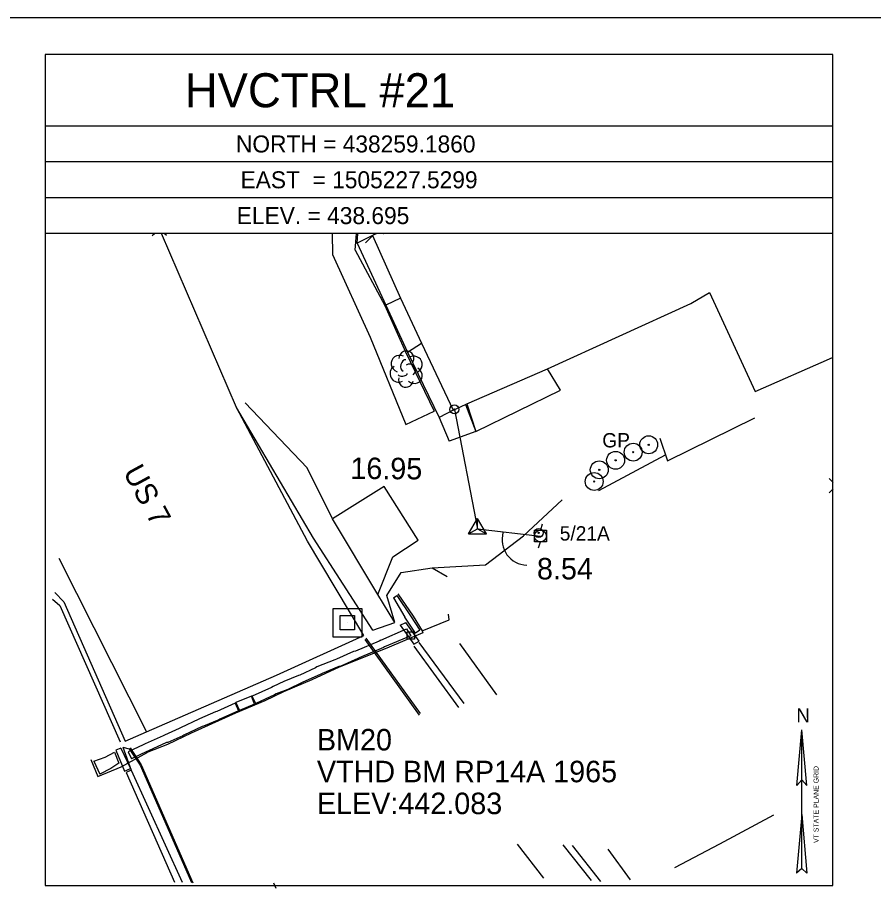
# Model space of a CAD drawing. Extents: x 1504239 to 1504879, y 438007 to 438427.
# Drawn here: x 1504390.4 to 1504509.9, y 438178.8 to 438300.4 of the extents above; entities that cross this region are included whole.
import ezdxf

# ---------------------------------------------------------------- set-up
doc = ezdxf.new("R2010")
doc.units = 0
for name, color, linetype in [('BDC', 7, 'Continuous'), ('BELB', 7, 'Continuous'), ('BF', 7, 'Continuous'), ('BR', 7, 'Continuous'), ('BSE', 7, 'Continuous'), ('BSUBM', 7, 'Continuous'), ('CBP', 7, 'Continuous'), ('CPBM', 7, 'Continuous'), ('CPSM', 7, 'Continuous'), ('Default', 7, 'Continuous'), ('DS', 7, 'Continuous'), ('L_TIC', 7, 'Continuous'), ('LAWE', 7, 'Continuous'), ('LBC', 7, 'Continuous'), ('LBF', 7, 'Continuous'), ('LDEFAULT', 7, 'Continuous'), ('LFNC', 7, 'Continuous'), ('LSH', 7, 'Continuous'), ('LW', 7, 'Continuous'), ('NBL2', 7, 'Continuous'), ('NNA_P', 7, 'Continuous'), ('P_TIC', 7, 'Continuous'), ('PET', 7, 'Continuous'), ('PSP', 7, 'Continuous'), ('R_A', 7, 'Continuous'), ('RDG', 7, 'Continuous'), ('RGP', 7, 'Continuous'), ('RGR', 7, 'Continuous'), ('RSW', 7, 'Continuous'), ('U_C', 7, 'Continuous'), ('UP', 7, 'Continuous'), ('UW', 7, 'Continuous')]:
    doc.layers.add(name, color=color, linetype=linetype)

msp = doc.modelspace()

# ---------------------------------------------------------------- linework, layer by layer
at = {"layer": 'BDC'}
for points in [[(1504439.02, 438213.73), (1504446.6, 438203.21)], [(1504405.08, 438198.52), (1504405.97, 438198.25), (1504407.53, 438196), (1504414.67, 438179.63)], [(1504460.16, 438184.96), (1504463.82, 438180.22)]]:
    msp.add_lwpolyline(points, dxfattribs=at)
at = {"layer": 'BELB'}
for points in [[(1504438.91, 438213.51), (1504446.49, 438202.97)], [(1504406.14, 438198.4), (1504407.65, 438196.02), (1504414.88, 438179.58)], [(1504426.53, 438178.76), (1504426.19, 438179.52)]]:
    msp.add_lwpolyline(points, dxfattribs=at)
at = {"layer": 'BF'}
for points in [[(1504446.42, 438213.09), (1504452.7, 438204.59)], [(1504405.08, 438198.52), (1504406.28, 438195.31), (1504405.56, 438194.98), (1504412.32, 438179.66)], [(1504467.85, 438184.78), (1504471.79, 438179.77)]]:
    msp.add_lwpolyline(points, dxfattribs=at)
at = {"layer": 'BR'}
for points in [[(1504443.84, 438215.51), (1504445.72, 438212.86), (1504446.47, 438213.29), (1504444.63, 438215.9)], [(1504443.84, 438215.51), (1504444.63, 438215.9)], [(1504445.71, 438212.58), (1504451.97, 438204.02)], [(1504404.81, 438198.38), (1504404.1, 438198.1), (1504405.34, 438195.14), (1504406.16, 438195.5)], [(1504404.81, 438198.38), (1504406.16, 438195.5)], [(1504406.28, 438195.31), (1504413.4, 438179.66)], [(1504466.55, 438184.88), (1504470.48, 438179.9)]]:
    msp.add_lwpolyline(points, dxfattribs=at)
at = {"layer": 'BSE'}
for points in [[(1504441.13, 438213.42), (1504444.71, 438215.03), (1504445.32, 438214.06), (1504441.65, 438212.49), (1504441.49, 438212.43), (1504438.1, 438210.97), (1504437.9, 438210.87), (1504435.56, 438209.82), (1504435.26, 438209.74), (1504432.93, 438208.79), (1504432.67, 438208.64), (1504430.22, 438207.56), (1504430.15, 438207.51), (1504428.12, 438206.56), (1504426.51, 438205.93), (1504426.27, 438205.79), (1504423.65, 438204.61), (1504423.5, 438204.52), (1504421.41, 438203.61), (1504421.25, 438203.59), (1504418.64, 438202.41), (1504418.5, 438202.33), (1504416.36, 438201.42), (1504416.18, 438201.37), (1504413.59, 438200.17), (1504413.48, 438200.08), (1504411.36, 438199.17), (1504411.21, 438199.13), (1504408.66, 438197.97), (1504408.43, 438197.88), (1504406.32, 438196.88)], [(1504441.13, 438213.42), (1504440.88, 438213.31), (1504437.59, 438211.91), (1504437.33, 438211.83), (1504434.94, 438210.78), (1504434.71, 438210.7), (1504432.19, 438209.7), (1504431.99, 438209.59), (1504429.81, 438208.57), (1504429.62, 438208.48), (1504427.56, 438207.68), (1504426.1, 438206.96), (1504425.85, 438206.84), (1504423.14, 438205.63), (1504423.04, 438205.63), (1504420.88, 438204.72), (1504420.77, 438204.62), (1504418.21, 438203.48), (1504418.05, 438203.42), (1504415.78, 438202.45), (1504415.72, 438202.41), (1504413.14, 438201.19), (1504412.97, 438201.1), (1504410.89, 438200.17), (1504410.71, 438200.09), (1504408.19, 438198.97), (1504407.93, 438198.84), (1504405.84, 438197.87), (1504406.32, 438196.88)], [(1504423.5, 438204.52), (1504423.04, 438205.63)], [(1504423.65, 438204.61), (1504423.14, 438205.63)], [(1504420.77, 438204.62), (1504421.25, 438203.59)], [(1504420.88, 438204.72), (1504421.41, 438203.61)]]:
    msp.add_lwpolyline(points, dxfattribs=at)
at = {"layer": 'BSUBM'}
for points in [[(1504443.5, 438219.88), (1504445.65, 438216.77), (1504446.91, 438214.75), (1504446.97, 438214.46), (1504441.98, 438212.32), (1504435.32, 438209.66), (1504431.51, 438207.88), (1504427.55, 438206.2), (1504424.91, 438204.98), (1504420.84, 438203.26), (1504414.65, 438200.45), (1504411.31, 438198.89), (1504408.59, 438197.82)], [(1504442.89, 438219.33), (1504443.36, 438219.69), (1504445.25, 438216.82), (1504446.59, 438214.82), (1504445.95, 438214.4), (1504444.49, 438216.65)], [(1504442.89, 438219.33), (1504444.49, 438216.65)], [(1504400.64, 438196.76), (1504401.61, 438194.4), (1504404.84, 438195.77), (1504408.59, 438197.82)], [(1504401.04, 438196.53), (1504402.62, 438197.08), (1504403.91, 438197.8), (1504404.55, 438196.27), (1504403.43, 438195.52), (1504401.87, 438194.75)], [(1504401.04, 438196.53), (1504401.87, 438194.75)]]:
    msp.add_lwpolyline(points, dxfattribs=at)
at = {"layer": 'CBP'}
for centre, radius in [((1504451.4, 438245.64), 0.625), ((1504451.4, 438245.64), 0.0833), ((1504463.16, 438228.41), 0.625), ((1504463.16, 438228.41), 0.0833)]:
    msp.add_circle(centre, radius, dxfattribs=at)
at = {"layer": 'CPBM'}
for p, q in [((1504444.82, 438213.58), (1504444.82, 438214.58)), ((1504444.82, 438214.58), (1504445.82, 438214.58)), ((1504445.32, 438214.08), (1504445.32, 438214.08)), ((1504445.32, 438214.08), (1504445.32, 438214.08)), ((1504445.82, 438214.58), (1504445.82, 438213.58)), ((1504445.82, 438213.58), (1504444.82, 438213.58))]:
    msp.add_line(p, q, dxfattribs=at)
at = {"layer": 'CPSM'}
for p, q in [((1504453.37, 438228.27), (1504454.62, 438230.43)), ((1504455.87, 438228.27), (1504454.62, 438230.43)), ((1504454.62, 438228.99), (1504454.62, 438230.43)), ((1504453.37, 438228.27), (1504454.62, 438228.99)), ((1504453.37, 438228.27), (1504455.87, 438228.27)), ((1504454.62, 438228.99), (1504454.62, 438228.99)), ((1504454.62, 438228.99), (1504455.87, 438228.27))]:
    msp.add_line(p, q, dxfattribs=at)
at = {"layer": 'Default'}
for p, q in [((1504451.4, 438245.64), (1504454.62, 438228.99)), ((1504454.62, 438228.99), (1504463.41, 438227.97))]:
    msp.add_line(p, q, dxfattribs=at)
msp.add_arc((1504461.62, 438227.47), 3.57, 164.1677, 268.104, dxfattribs=at)
at = {"layer": 'DS'}
for p, q in [((1504434.46, 438217.87), (1504438.46, 438217.87)), ((1504434.46, 438213.87), (1504434.46, 438217.87)), ((1504438.46, 438217.87), (1504438.46, 438213.87)), ((1504435.46, 438214.87), (1504435.46, 438216.87)), ((1504435.46, 438216.87), (1504437.46, 438216.87)), ((1504437.46, 438216.87), (1504437.46, 438214.87)), ((1504437.46, 438214.87), (1504435.46, 438214.87)), ((1504436.46, 438215.87), (1504436.46, 438215.87)), ((1504436.46, 438215.87), (1504436.46, 438215.87)), ((1504438.46, 438213.87), (1504434.46, 438213.87))]:
    msp.add_line(p, q, dxfattribs=at)
at = {"layer": 'L_TIC'}
for points in [[(1504438.96, 438268.9), (1504440.28, 438270.22)], [(1504441.45, 438270.19), (1504441.48, 438270.22)], [(1504441.45, 438270.19), (1504441.48, 438270.22)], [(1504443.45, 438270.19), (1504443.43, 438270.22)], [(1504443.45, 438270.19), (1504443.43, 438270.22)], [(1504504.28, 438235.44), (1504503.72, 438236)], [(1504503.72, 438234), (1504504.28, 438234.56)]]:
    msp.add_lwpolyline(points, dxfattribs=at)
at = {"layer": 'LAWE'}
msp.add_lwpolyline([(1504495.94, 438189), (1504488.42, 438184.94), (1504482.15, 438181.66)], dxfattribs=at)
at = {"layer": 'LBC'}
msp.add_lwpolyline([(1504440.57, 438270.22), (1504439.96, 438269.9), (1504443.86, 438261.19), (1504446.81, 438254.89), (1504451.23, 438245.55), (1504452.93, 438246.31), (1504453.14, 438246.41), (1504464.38, 438251.31), (1504484.42, 438260.44), (1504487.01, 438261.98), (1504493.39, 438248.16), (1504503.79, 438252.7), (1504504.28, 438252.93)], dxfattribs=at)
at = {"layer": 'LBF'}
for points in [[(1504439.96, 438269.9), (1504437.83, 438268.83), (1504437.92, 438270.22)], [(1504443.86, 438261.19), (1504441.82, 438260.2), (1504444.84, 438253.65), (1504446.81, 438254.89)], [(1504453.14, 438246.41), (1504454.39, 438242.55), (1504466.21, 438248.35), (1504464.38, 438251.31)], [(1504451.23, 438245.55), (1504449.26, 438244.53), (1504450.66, 438241.23)], [(1504452.93, 438246.31), (1504454.39, 438242.55)], [(1504454.39, 438242.55), (1504450.66, 438241.23)]]:
    msp.add_lwpolyline(points, dxfattribs=at)
at = {"layer": 'LDEFAULT'}
msp.add_lwpolyline([(1504480.84, 438239.24), (1504471.53, 438234.27)], dxfattribs=at)
at = {"layer": 'LFNC'}
msp.add_lwpolyline([(1504480.09, 438241.62), (1504481.16, 438238.45), (1504493.37, 438244.45)], dxfattribs=at)
at = {"layer": 'LSH'}
msp.add_line((1504444.64, 438251.32), (1504444.64, 438251.32), dxfattribs=at)
msp.add_line((1504444.64, 438251.32), (1504444.64, 438251.32), dxfattribs=at)
msp.add_arc((1504444.69, 438252.75), 1.05, 335.5272, 180.9563, dxfattribs=at)
for centre, major_axis, ratio, start_param, end_param in [((1504443.85, 438251.98), (1.21, -0.51), 0.895232, 1.570796, 4.712389), ((1504444.43, 438251.78), (-0.208, -0.792), 0.645439, 3.141593, 6.283185), ((1504445.68, 438251.9), (-1.14, -0.48), 0.949671, 1.570796, 4.712389), ((1504443.56, 438250.61), (0.58, -1.04), 0.959034, 3.141593, 6.283185), ((1504445.14, 438251.15), (-0.5, 0.667), 0.989748, 3.141593, 6.283185), ((1504445.64, 438250.49), (-1.09, 0.79), 0.841452, 1.570796, 4.712389), ((1504444.18, 438250.57), (-0.625, -0.083), 0.423636, 0, 3.141593), ((1504444.64, 438249.82), (0.26, 1.06), 0.942809, 1.570796, 4.712389)]:
    msp.add_ellipse(centre, major_axis=major_axis, ratio=ratio, start_param=start_param, end_param=end_param, dxfattribs=at)
at = {"layer": 'LW'}
for points in [[(1504437.83, 438268.83), (1504441.82, 438260.2)], [(1504444.84, 438253.65), (1504449.26, 438244.53)], [(1504448.29, 438223.54), (1504455.73, 438223.94)], [(1504446.91, 438214.75), (1504450.67, 438216.27), (1504450.56, 438217.07)]]:
    msp.add_lwpolyline(points, dxfattribs=at)
at = {"layer": 'NBL2'}
for p, q in [((1504239.27, 438300.36), (1504879.27, 438300.36)), ((1504504.27, 438285.19), (1504394.27, 438285.19)), ((1504504.27, 438280.19), (1504394.27, 438280.19)), ((1504504.27, 438275.19), (1504394.27, 438275.19)), ((1504504.27, 438270.19), (1504394.27, 438270.19))]:
    msp.add_line(p, q, dxfattribs=at)
msp.add_lwpolyline([(1504394.27, 438179.19), (1504504.27, 438179.19), (1504504.27, 438295.19), (1504394.27, 438295.19)], close=True, dxfattribs=at)
at = {"layer": 'NNA_P'}
for p, q in [((1504499.22, 438193.15), (1504499.91, 438200.94)), ((1504499.91, 438181.57), (1504499.91, 438200.94)), ((1504500.6, 438193.15), (1504499.91, 438200.94)), ((1504499.22, 438193.15), (1504499.91, 438193.92)), ((1504500.61, 438193.15), (1504499.91, 438193.92)), ((1504499.91, 438189.09), (1504499.19, 438180.93)), ((1504499.91, 438189.09), (1504500.63, 438180.93)), ((1504499.91, 438181.57), (1504499.19, 438180.93)), ((1504499.91, 438181.57), (1504500.63, 438180.93))]:
    msp.add_line(p, q, dxfattribs=at)
at = {"layer": 'P_TIC'}
for points in [[(1504409.18, 438269.9), (1504409.5, 438270.22)], [(1504411.18, 438269.9), (1504410.87, 438270.22)]]:
    msp.add_lwpolyline(points, dxfattribs=at)
at = {"layer": 'PET'}
msp.add_lwpolyline([(1504396.15, 438224.86), (1504408.42, 438200.64), (1504426.55, 438208.57), (1504438.75, 438214.09), (1504430.87, 438227.26), (1504420.96, 438245.89), (1504410.48, 438270.22)], dxfattribs=at)
at = {"layer": 'PSP'}
msp.add_lwpolyline([(1504395.58, 438220.11), (1504396.87, 438218.79), (1504405.41, 438199.33), (1504408.42, 438200.64)], dxfattribs=at)
at = {"layer": 'RDG'}
msp.add_lwpolyline([(1504440.7, 438219.82), (1504442.78, 438225.07), (1504446.36, 438227.37), (1504441.6, 438234.9), (1504437.88, 438232.57), (1504434.37, 438230.38)], dxfattribs=at)
at = {"layer": 'RGP'}
for p, q in [((1504478.53, 438240.71), (1504478.53, 438240.71)), ((1504476.37, 438239.68), (1504476.37, 438239.68)), ((1504473.91, 438238.54), (1504473.91, 438238.54)), ((1504471.63, 438237.21), (1504471.63, 438237.21)), ((1504470.92, 438235.58), (1504470.92, 438235.58))]:
    msp.add_line(p, q, dxfattribs=at)
for centre, radius in [((1504478.53, 438240.71), 1.25), ((1504476.37, 438239.68), 1.25), ((1504478.53, 438240.71), 0.0833), ((1504473.91, 438238.54), 1.25), ((1504476.37, 438239.68), 0.0833), ((1504471.63, 438237.21), 1.25), ((1504473.91, 438238.54), 0.0833), ((1504470.92, 438235.58), 1.25), ((1504471.63, 438237.21), 0.0833), ((1504470.92, 438235.58), 0.0833)]:
    msp.add_circle(centre, radius, dxfattribs=at)
at = {"layer": 'RGR'}
for points in [[(1504455.73, 438223.94), (1504461.05, 438227.99), (1504466.43, 438233.03)], [(1504443.1, 438215.88), (1504441.94, 438219.67), (1504443.95, 438222.87), (1504448.29, 438223.54), (1504450.4, 438222.3)], [(1504395.28, 438219.17), (1504396.28, 438218.29), (1504404.7, 438199.26)]]:
    msp.add_lwpolyline(points, dxfattribs=at)
at = {"layer": 'RSW'}
for points in [[(1504434.35, 438270.22), (1504434.38, 438267.26), (1504439.62, 438255.75), (1504444.63, 438243.55), (1504448.55, 438245.42)], [(1504437.53, 438267.86), (1504437.72, 438270.22)], [(1504437.53, 438267.86), (1504441.68, 438260.15), (1504444.58, 438253.69), (1504448.55, 438245.42)], [(1504440.01, 438214.85), (1504443.1, 438215.88), (1504440.7, 438219.82), (1504434.37, 438230.38), (1504430.83, 438237.49), (1504422.2, 438246.56)], [(1504440.01, 438214.85), (1504431.73, 438227.67), (1504420.96, 438245.89)]]:
    msp.add_lwpolyline(points, dxfattribs=at)
at = {"layer": 'UP'}
for p, q in [((1504463.66, 438229.64), (1504463.41, 438228.8)), ((1504462.58, 438227.14), (1504462.58, 438228.8)), ((1504462.58, 438228.8), (1504464.25, 438228.8)), ((1504464.25, 438228.8), (1504464.25, 438227.14)), ((1504464.25, 438227.14), (1504462.58, 438227.14)), ((1504463.16, 438226.3), (1504463.41, 438227.14)), ((1504463.41, 438227.97), (1504463.41, 438227.97))]:
    msp.add_line(p, q, dxfattribs=at)
msp.add_circle((1504463.41, 438227.97), 0.833, dxfattribs=at)
at = {"layer": 'UW'}
for points in [[(1504457.34, 438205.81), (1504452.17, 438212.98)], [(1504475.97, 438179.98), (1504472.87, 438184.27)]]:
    msp.add_lwpolyline(points, dxfattribs=at)

# ---------------------------------------------------------------- texts
at = {"layer": 'Default'}
for s, rotation, p in [('US 7', 298.4894, (1504405.06, 438236.9)), ('16.95', 359.6069, (1504436.86, 438235.94)), ('8.54', 0.1001, (1504462.93, 438221.91))]:
    msp.add_text(s, height=3, rotation=rotation, dxfattribs=at).set_placement(p)
for s, p in [('BM20', (1504432.2, 438198.04)), ('VTHD BM RP14A 1965', (1504432.2, 438193.6)), ('ELEV:442.083', (1504432.2, 438189.15))]:
    msp.add_text(s, height=3, dxfattribs=at).set_placement(p)
at = {"layer": 'NBL2'}
for s, height, p in [('     HVCTRL #21    ', 4.75, (1504404.92, 438287.82)), ('NORTH = 438259.1860 ', 2.375, (1504420.89, 438281.51)), ('EAST  = 1505227.5299', 2.375, (1504421.53, 438276.51)), ('ELEV. = 438.695     ', 2.375, (1504421, 438271.51))]:
    msp.add_text(s, height=height, dxfattribs=at).set_placement(p)
at = {"layer": 'NNA_P'}
msp.add_text('N', height=1.97, dxfattribs=at).set_placement((1504499.15, 438201.95))
msp.add_text('VT STATE PLANE GRID', height=0.7, rotation=90.0204, dxfattribs=at).set_placement((1504502.26, 438185.13))
at = {"layer": 'R_A'}
msp.add_text('GP', height=2, dxfattribs=at).set_placement((1504472.05, 438240.34))
at = {"layer": 'U_C'}
msp.add_text('5/21A', height=2, dxfattribs=at).set_placement((1504466.11, 438227.34))

doc.saveas('drawing.dxf')
